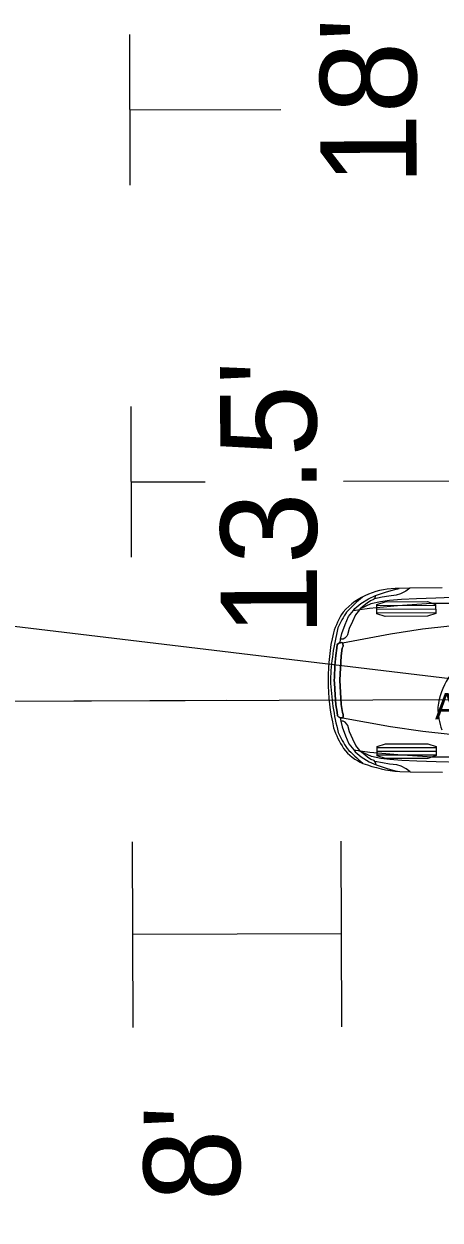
# Model space of a CAD drawing. Extents: x 17465868 to 18455672, y 7253752 to 7478845.
# Drawn here: x 18455117.28 to 18455133.23, y 7478799.19 to 7478844.97 of the extents above; entities that cross this region are included whole.
import ezdxf

# ---------------------------------------------------------------- set-up
doc = ezdxf.new("R2010")
doc.units = 0
for name, color, linetype in [('Clinton 225 CL Girders', 7, 'Continuous'), ('Clinton 225 CL Truss', 7, 'Continuous'), ('Clinton 225 Handrail', 7, 'Continuous'), ('Clinton 225 Metal Rail', 7, 'Continuous')]:
    doc.layers.add(name, color=color, linetype=linetype)

msp = doc.modelspace()

# ---------------------------------------------------------------- linework, layer by layer
at = {"layer": 'Clinton 225 CL Girders'}
for p, q in [((18455121.358, 7478838.796), (18455121.339, 7478844.568)), ((18455121.349, 7478841.682), (18455127.121, 7478841.701)), ((18455140.106, 7478819.122), (18455015.19, 7478818.707))]:
    msp.add_line(p, q, dxfattribs=at)
at = {"layer": 'Clinton 225 CL Truss'}
msp.add_line((18455125.031, 7478819.072), (18454975.369, 7478818.574), dxfattribs=at)
for centre, radius, start, end in [((18455135.855, 7478818.479), 2.738, 122.7505, 172.8661), ((18455136.279, 7478818.909), 3.142, 181.6432, 197.7735)]:
    msp.add_arc(centre, radius, start, end, dxfattribs=at)
at = {"layer": 'Clinton 225 Handrail'}
for p, q in [((18455121.406, 7478824.557), (18455121.387, 7478830.328)), ((18455121.396, 7478827.443), (18455124.22, 7478827.452)), ((18455129.52, 7478827.47), (18455134.915, 7478827.488)), ((18455672.262, 7478755.205), (18455083.514, 7478825.92)), ((18455130.487, 7478822.974), (18455130.755, 7478823.102)), ((18455130.755, 7478823.102), (18455130.731, 7478823.008)), ((18455130.755, 7478823.102), (18455131.173, 7478823.239)), ((18455131.265, 7478823.071), (18455131, 7478823.028)), ((18455131.173, 7478823.239), (18455131.491, 7478823.325)), ((18455131.547, 7478823.106), (18455131.265, 7478823.071)), ((18455131.491, 7478823.325), (18455131.659, 7478823.359)), ((18455131.715, 7478823.157), (18455131.547, 7478823.106)), ((18455132.061, 7478823.372), (18455131.659, 7478823.359)), ((18455131.909, 7478823.259), (18455131.715, 7478823.157)), ((18455132.061, 7478823.372), (18455131.909, 7478823.259)), ((18455133.304, 7478823.39), (18455132.061, 7478823.372)), ((18455129.903, 7478822.521), (18455129.959, 7478822.597)), ((18455129.959, 7478822.597), (18455130.192, 7478822.794)), ((18455130.146, 7478822.555), (18455130.516, 7478822.605)), ((18455130.577, 7478822.773), (18455130.164, 7478822.581)), ((18455130.323, 7478822.707), (18455130.164, 7478822.581)), ((18455130.192, 7478822.794), (18455130.487, 7478822.974)), ((18455130.43, 7478822.805), (18455130.323, 7478822.707)), ((18455130.561, 7478822.893), (18455130.43, 7478822.805)), ((18455130.516, 7478822.605), (18455131.59, 7478822.712)), ((18455130.68, 7478822.937), (18455130.561, 7478822.893)), ((18455130.939, 7478822.85), (18455130.577, 7478822.773)), ((18455130.709, 7478822.964), (18455130.68, 7478822.937)), ((18455131, 7478823.028), (18455130.709, 7478822.964)), ((18455130.731, 7478823.008), (18455130.709, 7478822.964)), ((18455130.805, 7478822.716), (18455133.055, 7478822.722)), ((18455131.283, 7478822.902), (18455130.939, 7478822.85)), ((18455131.742, 7478822.937), (18455131.283, 7478822.902)), ((18455131.59, 7478822.712), (18455132.899, 7478822.8)), ((18455132.316, 7478822.972), (18455131.742, 7478822.937)), ((18455133.057, 7478823), (18455132.316, 7478822.972)), ((18455132.899, 7478822.8), (18455133.746, 7478822.803)), ((18455134.011, 7478823.028), (18455133.057, 7478823)), ((18455129.592, 7478821.986), (18455129.721, 7478822.286)), ((18455129.721, 7478822.286), (18455129.903, 7478822.521)), ((18455129.988, 7478822.357), (18455129.864, 7478822.106)), ((18455129.903, 7478822.521), (18455130.146, 7478822.555)), ((18455130.141, 7478822.548), (18455129.988, 7478822.357)), ((18455130.164, 7478822.581), (18455130.141, 7478822.548)), ((18455130.805, 7478822.575), (18455133.055, 7478822.581)), ((18455130.806, 7478822.434), (18455133.056, 7478822.441)), ((18455129.467, 7478821.642), (18455129.592, 7478821.986)), ((18455129.74, 7478821.828), (18455129.678, 7478821.588)), ((18455129.864, 7478822.106), (18455129.74, 7478821.828)), ((18455131.32, 7478821.635), (18455132.548, 7478821.824)), ((18455132.548, 7478821.824), (18455133.604, 7478821.941)), ((18455129.329, 7478821.255), (18455129.286, 7478821.215)), ((18455129.286, 7478821.215), (18455129.329, 7478821.255)), ((18455129.371, 7478821.283), (18455129.329, 7478821.255)), ((18455129.329, 7478821.255), (18455129.371, 7478821.283)), ((18455129.406, 7478821.289), (18455129.371, 7478821.283)), ((18455129.371, 7478821.283), (18455129.406, 7478821.289)), ((18455129.392, 7478821.287), (18455129.411, 7478821.419)), ((18455129.449, 7478821.296), (18455129.406, 7478821.289)), ((18455129.406, 7478821.289), (18455129.449, 7478821.296)), ((18455129.411, 7478821.419), (18455129.467, 7478821.642)), ((18455129.457, 7478821.419), (18455129.411, 7478821.419)), ((18455129.484, 7478821.29), (18455129.449, 7478821.296)), ((18455129.449, 7478821.296), (18455129.484, 7478821.29)), ((18455129.508, 7478821.424), (18455129.457, 7478821.419)), ((18455129.484, 7478821.29), (18455131.32, 7478821.635)), ((18455129.498, 7478821.263), (18455129.484, 7478821.29)), ((18455129.484, 7478821.29), (18455129.498, 7478821.263)), ((18455129.506, 7478821.161), (18455129.498, 7478821.263)), ((18455129.498, 7478821.263), (18455129.506, 7478821.161)), ((18455129.582, 7478821.457), (18455129.508, 7478821.424)), ((18455129.65, 7478821.534), (18455129.582, 7478821.457)), ((18455129.678, 7478821.588), (18455129.65, 7478821.534)), ((18455129.231, 7478820.794), (18455129.197, 7478820.415)), ((18455129.197, 7478820.415), (18455129.231, 7478820.794)), ((18455129.273, 7478821.079), (18455129.231, 7478820.794)), ((18455129.231, 7478820.794), (18455129.273, 7478821.079)), ((18455129.286, 7478821.215), (18455129.273, 7478821.079)), ((18455129.273, 7478821.079), (18455129.286, 7478821.215)), ((18455129.383, 7478819.852), (18455129.436, 7478820.781)), ((18455129.436, 7478820.781), (18455129.383, 7478819.852)), ((18455129.436, 7478820.781), (18455129.478, 7478821.086)), ((18455129.478, 7478821.086), (18455129.436, 7478820.781)), ((18455129.478, 7478821.086), (18455129.506, 7478821.161)), ((18455129.506, 7478821.161), (18455129.478, 7478821.086)), ((18455129.197, 7478820.415), (18455129.177, 7478819.961)), ((18455129.177, 7478819.961), (18455129.197, 7478820.415)), ((18455129.177, 7478819.961), (18455129.17, 7478819.852)), ((18455129.17, 7478819.852), (18455129.177, 7478819.961)), ((18455129.17, 7478819.852), (18455129.177, 7478819.743)), ((18455129.177, 7478819.743), (18455129.17, 7478819.852)), ((18455129.441, 7478818.924), (18455129.383, 7478819.852)), ((18455129.383, 7478819.852), (18455129.441, 7478818.924)), ((18455129.177, 7478819.743), (18455129.2, 7478819.289)), ((18455129.2, 7478819.289), (18455129.177, 7478819.743)), ((18455129.2, 7478819.289), (18455129.236, 7478818.91)), ((18455129.236, 7478818.91), (18455129.2, 7478819.289)), ((18455129.236, 7478818.91), (18455129.28, 7478818.625)), ((18455129.28, 7478818.625), (18455129.236, 7478818.91)), ((18455129.28, 7478818.625), (18455129.294, 7478818.49)), ((18455129.294, 7478818.49), (18455129.28, 7478818.625)), ((18455129.294, 7478818.49), (18455129.337, 7478818.449)), ((18455129.337, 7478818.449), (18455129.294, 7478818.49)), ((18455129.485, 7478818.619), (18455129.441, 7478818.924)), ((18455129.441, 7478818.924), (18455129.485, 7478818.619)), ((18455129.513, 7478818.544), (18455129.485, 7478818.619)), ((18455129.485, 7478818.619), (18455129.513, 7478818.544)), ((18455129.506, 7478818.443), (18455129.513, 7478818.544)), ((18455129.513, 7478818.544), (18455129.506, 7478818.443)), ((18455129.337, 7478818.449), (18455129.379, 7478818.422)), ((18455129.379, 7478818.422), (18455129.337, 7478818.449)), ((18455129.379, 7478818.422), (18455129.414, 7478818.415)), ((18455129.414, 7478818.415), (18455129.379, 7478818.422)), ((18455129.4, 7478818.418), (18455129.42, 7478818.286)), ((18455129.414, 7478818.415), (18455129.457, 7478818.409)), ((18455129.457, 7478818.409), (18455129.414, 7478818.415)), ((18455129.42, 7478818.286), (18455129.477, 7478818.063)), ((18455129.465, 7478818.286), (18455129.42, 7478818.286)), ((18455129.457, 7478818.409), (18455129.492, 7478818.416)), ((18455129.492, 7478818.416), (18455129.457, 7478818.409)), ((18455129.517, 7478818.281), (18455129.465, 7478818.286)), ((18455129.477, 7478818.063), (18455129.603, 7478817.72)), ((18455129.492, 7478818.416), (18455129.506, 7478818.443)), ((18455129.506, 7478818.443), (18455129.492, 7478818.416)), ((18455129.492, 7478818.416), (18455131.33, 7478818.08)), ((18455129.591, 7478818.249), (18455129.517, 7478818.281)), ((18455129.659, 7478818.172), (18455129.591, 7478818.249)), ((18455129.688, 7478818.118), (18455129.659, 7478818.172)), ((18455129.751, 7478817.878), (18455129.688, 7478818.118)), ((18455131.33, 7478818.08), (18455132.559, 7478817.898)), ((18455129.603, 7478817.72), (18455129.735, 7478817.421)), ((18455129.877, 7478817.601), (18455129.751, 7478817.878)), ((18455130.002, 7478817.351), (18455129.877, 7478817.601)), ((18455132.559, 7478817.898), (18455133.616, 7478817.787)), ((18455129.735, 7478817.421), (18455129.918, 7478817.187)), ((18455129.918, 7478817.187), (18455129.975, 7478817.111)), ((18455129.918, 7478817.187), (18455130.161, 7478817.154)), ((18455129.975, 7478817.111), (18455130.208, 7478816.915)), ((18455130.156, 7478817.16), (18455130.002, 7478817.351)), ((18455130.179, 7478817.128), (18455130.156, 7478817.16)), ((18455130.161, 7478817.154), (18455130.532, 7478817.106)), ((18455130.339, 7478817.003), (18455130.179, 7478817.128)), ((18455130.593, 7478816.938), (18455130.179, 7478817.128)), ((18455130.532, 7478817.106), (18455131.606, 7478817.005)), ((18455130.82, 7478817.278), (18455133.07, 7478817.284)), ((18455130.821, 7478817.138), (18455133.071, 7478817.144)), ((18455130.208, 7478816.915), (18455130.504, 7478816.736)), ((18455130.447, 7478816.905), (18455130.339, 7478817.003)), ((18455130.578, 7478816.818), (18455130.447, 7478816.905)), ((18455130.504, 7478816.736), (18455130.774, 7478816.611)), ((18455130.697, 7478816.775), (18455130.578, 7478816.818)), ((18455130.956, 7478816.863), (18455130.593, 7478816.938)), ((18455130.726, 7478816.748), (18455130.697, 7478816.775)), ((18455130.749, 7478816.704), (18455130.726, 7478816.748)), ((18455131.018, 7478816.686), (18455130.726, 7478816.748)), ((18455130.774, 7478816.611), (18455130.749, 7478816.704)), ((18455130.821, 7478816.997), (18455133.071, 7478817.003)), ((18455131.3, 7478816.813), (18455130.956, 7478816.863)), ((18455131.283, 7478816.644), (18455131.018, 7478816.686)), ((18455131.565, 7478816.611), (18455131.283, 7478816.644)), ((18455131.759, 7478816.781), (18455131.3, 7478816.813)), ((18455131.606, 7478817.005), (18455132.916, 7478816.924)), ((18455132.333, 7478816.749), (18455131.759, 7478816.781)), ((18455133.075, 7478816.725), (18455132.333, 7478816.749)), ((18455132.916, 7478816.924), (18455133.763, 7478816.926)), ((18455134.029, 7478816.703), (18455133.075, 7478816.725)), ((18455130.774, 7478816.611), (18455131.192, 7478816.475)), ((18455131.192, 7478816.475), (18455131.51, 7478816.391)), ((18455131.51, 7478816.391), (18455131.678, 7478816.358)), ((18455131.733, 7478816.561), (18455131.565, 7478816.611)), ((18455131.678, 7478816.358), (18455132.081, 7478816.348)), ((18455131.928, 7478816.46), (18455131.733, 7478816.561)), ((18455132.081, 7478816.348), (18455131.928, 7478816.46)), ((18455132.081, 7478816.348), (18455133.323, 7478816.337)), ((18455121.466, 7478806.563), (18455121.442, 7478813.666)), ((18455129.465, 7478806.59), (18455129.442, 7478813.693)), ((18455129.454, 7478810.141), (18455121.454, 7478810.115))]:
    msp.add_line(p, q, dxfattribs=at)
for points in [[(18455130.806, 7478822.4), (18455130.805, 7478822.751), (18455131.12, 7478822.857), (18455132.74, 7478822.862), (18455133.055, 7478822.757), (18455133.056, 7478822.406), (18455132.741, 7478822.299), (18455131.121, 7478822.295)], [(18455130.821, 7478816.962), (18455130.82, 7478817.313), (18455131.135, 7478817.42), (18455132.755, 7478817.424), (18455133.07, 7478817.319), (18455133.071, 7478816.968), (18455132.756, 7478816.862), (18455131.136, 7478816.857)]]:
    msp.add_lwpolyline(points, close=True, dxfattribs=at)
for centre, radius, start, end in [((18455131.542, 7478820.624), 2.738, 87.6904, 137.806), ((18455135.237, 7478817.181), 7.691, 130.4178, 136.6274), ((18455132.136, 7478820.733), 3.142, 146.5831, 162.7134), ((18455133.2, 7478820.123), 4.255, 146.6338, 156.0118), ((18455138.946, 7478819.437), 9.932, 165.9215, 177.6082), ((18455136.684, 7478819.922), 7.747, 166.9859, 180.5217), ((18455136.685, 7478819.824), 7.747, 179.7981, 193.3339), ((18455138.944, 7478820.321), 9.932, 182.7116, 194.3982), ((18455132.174, 7478819.003), 3.177, 197.6978, 213.6452), ((18455133.202, 7478819.603), 4.255, 204.3079, 213.6859), ((18455130.923, 7478818.287), 1.743, 216.8423, 247.9285), ((18455135.222, 7478822.556), 7.691, 223.6925, 229.9018), ((18455132.095, 7478821.544), 5.203, 249.4417, 265.3993)]:
    msp.add_arc(centre, radius, start, end, dxfattribs=at)
at = {"layer": 'Clinton 225 Metal Rail'}
msp.add_line((18455146.906, 7478819.145), (18454997.244, 7478818.647), dxfattribs=at)
for centre, radius, start, end in [((18455135.855, 7478818.479), 2.738, 122.7505, 172.8661), ((18455136.279, 7478818.909), 3.142, 181.6432, 197.7735)]:
    msp.add_arc(centre, radius, start, end, dxfattribs=at)

# ---------------------------------------------------------------- texts
at = {"layer": 'Clinton 225 CL Girders'}
msp.add_text("18'", height=3.6877, rotation=90.1905, dxfattribs=at).set_placement((18455132.327, 7478838.805))
at = {"layer": 'Clinton 225 Handrail'}
for s, height, rotation, p in [("13.5'", 3.6877, 90.1905, (18455128.515, 7478821.558)), ('AASHTO 2018 (US)', 1, 0.1599, (18455133.031, 7478818.357)), ("8'", 3.6877, 90.1905, (18455125.564, 7478799.918))]:
    msp.add_text(s, height=height, rotation=rotation, dxfattribs=at).set_placement(p)

doc.saveas('drawing.dxf')
